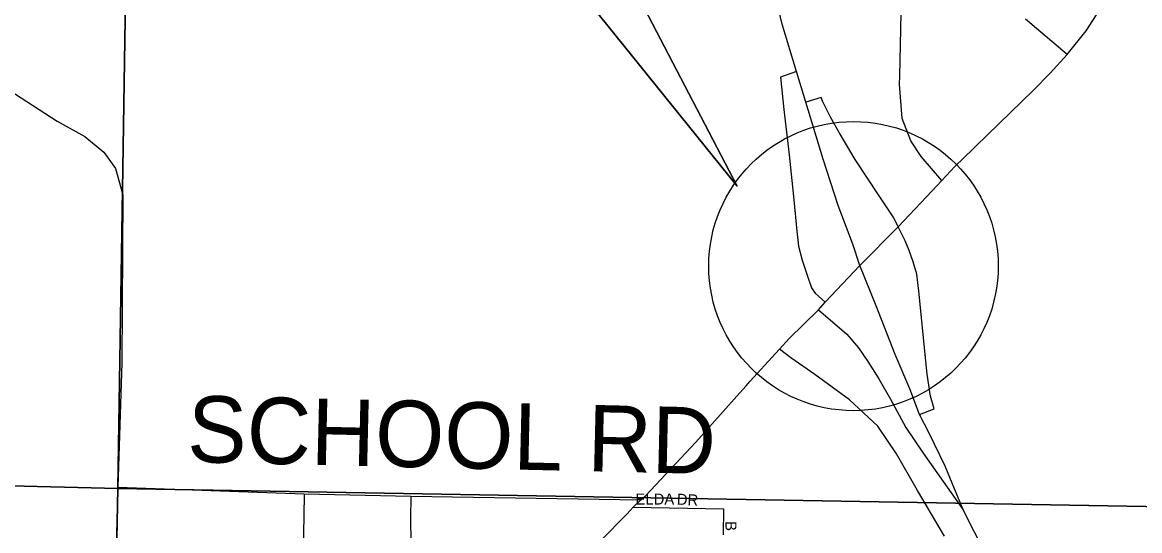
# Model space of a CAD drawing. Extents: x 0 to 34, y -2.3 to 22.
# Drawn here: x 5.22 to 6.175, y 15.386 to 15.821 of the extents above; entities that cross this region are included whole.
import ezdxf

# ---------------------------------------------------------------- set-up
doc = ezdxf.new("R2010")
doc.units = 0
for name, color, linetype in [('GM_X_County_Road', 7, 'Continuous'), ('GM_X_County_Road_Text', 7, 'Continuous'), ('GM_X_Interchange_Ramps', 7, 'Continuous'), ('GM_X_Section', 7, 'Continuous'), ('GM_X_State_Route', 7, 'Continuous'), ('GM_X_Township_Road', 7, 'Continuous'), ('GM_X_Township_Subdivision', 7, 'Continuous'), ('GM_X_Township_Subdivision_Text', 7, 'Continuous'), ('GM_X_US_Route', 7, 'Continuous'), ('SH_Text', 7, 'Continuous')]:
    doc.layers.add(name, color=color, linetype=linetype)

msp = doc.modelspace()

# ---------------------------------------------------------------- linework, layer by layer
at = {"layer": 'GM_X_County_Road'}
for p, q in [((5.13388, 15.8111), (5.24961, 15.73664)), ((5.24961, 15.73664), (5.27317, 15.72357)), ((5.27317, 15.72357), (5.28951, 15.71015)), ((5.28951, 15.71015), (5.29931, 15.69623)), ((5.29931, 15.69623), (5.30567, 15.67364)), ((5.30567, 15.67364), (5.30481, 15.52995)), ((5.30481, 15.52995), (5.30141, 15.42345)), ((5.30141, 15.42345), (5.29588, 15.22751)), ((5.30141, 15.42345), (5.46049, 15.41784)), ((5.46049, 15.41784), (5.5518, 15.41586)), ((5.5518, 15.41586), (5.74844, 15.41261))]:
    msp.add_line(p, q, dxfattribs=at)
at = {"layer": 'GM_X_Interchange_Ramps'}
for p, q in [((5.88133, 15.77914), (5.86757, 15.77434)), ((5.86757, 15.77434), (5.8706, 15.74657)), ((5.90238, 15.75687), (5.88938, 15.75297)), ((5.90394, 15.75313), (5.90238, 15.75687)), ((5.8706, 15.74657), (5.87504, 15.70775)), ((5.91043, 15.73995), (5.90394, 15.75313)), ((5.91785, 15.72682), (5.91043, 15.73995)), ((5.93165, 15.70393), (5.91785, 15.72682)), ((5.87504, 15.70775), (5.87906, 15.66943)), ((5.95154, 15.67369), (5.93165, 15.70393)), ((5.96443, 15.6539), (5.95154, 15.67369)), ((5.87906, 15.66943), (5.88158, 15.64252)), ((5.96829, 15.6463), (5.96443, 15.6539)), ((5.88158, 15.64252), (5.88316, 15.62961)), ((5.971, 15.64065), (5.96829, 15.6463)), ((5.97425, 15.63415), (5.971, 15.64065)), ((5.97769, 15.62606), (5.97425, 15.63415)), ((5.88316, 15.62961), (5.88628, 15.61771)), ((5.9812, 15.61643), (5.97769, 15.62606)), ((5.88628, 15.61771), (5.89056, 15.6049)), ((5.98421, 15.60565), (5.9812, 15.61643)), ((5.89056, 15.6049), (5.89432, 15.59408)), ((5.98586, 15.59117), (5.98421, 15.60565)), ((5.89432, 15.59408), (5.89736, 15.58942)), ((5.89736, 15.58942), (5.90591, 15.58167)), ((5.98813, 15.56876), (5.98586, 15.59117)), ((5.99131, 15.53692), (5.98813, 15.56876)), ((5.99316, 15.52032), (5.99131, 15.53692)), ((5.99599, 15.50128), (5.99316, 15.52032)), ((5.99893, 15.49052), (5.99599, 15.50128)), ((5.98655, 15.48577), (5.99893, 15.49052))]:
    msp.add_line(p, q, dxfattribs=at)
at = {"layer": 'GM_X_Section'}
for p, q in [((5.31637, 16.38127), (5.30144, 15.42241)), ((5.30144, 15.42241), (5.31637, 16.38127)), ((5.30144, 15.42241), (4.29924, 15.44635)), ((4.29924, 15.44635), (5.30144, 15.42241)), ((5.30144, 15.42241), (5.2785, 14.42965)), ((5.2785, 14.42965), (5.30144, 15.42241)), ((6.48214, 15.40173), (5.30144, 15.42241)), ((5.30144, 15.42241), (6.48214, 15.40173))]:
    msp.add_line(p, q, dxfattribs=at)
at = {"layer": 'GM_X_State_Route'}
for p, q in [((6.12891, 15.81387), (6.14031, 15.83145)), ((6.11275, 15.79357), (6.12891, 15.81387)), ((6.09814, 15.77772), (6.11275, 15.79357)), ((6.08365, 15.7629), (6.09814, 15.77772)), ((6.06427, 15.74418), (6.08365, 15.7629)), ((6.03463, 15.7152), (6.06427, 15.74418)), ((6.01673, 15.69778), (6.03224, 15.71287)), ((6.03224, 15.71287), (6.03463, 15.7152)), ((6.00549, 15.68589), (6.01673, 15.69778)), ((5.99247, 15.67188), (6.00549, 15.68589)), ((5.96829, 15.6463), (5.99247, 15.67188)), ((5.9355, 15.61313), (5.96829, 15.6463)), ((5.90591, 15.58167), (5.9355, 15.61313)), ((5.87504, 15.5507), (5.90021, 15.57511)), ((5.90021, 15.57511), (5.90591, 15.58167)), ((5.90021, 15.57511), (5.92452, 15.55438)), ((5.86678, 15.54156), (5.87504, 15.5507)), ((5.92452, 15.55438), (5.93439, 15.54274)), ((5.8415, 15.51395), (5.86678, 15.54156)), ((5.93439, 15.54274), (5.94233, 15.53093)), ((5.94233, 15.53093), (5.95185, 15.51612)), ((5.83035, 15.50129), (5.83829, 15.51031)), ((5.83829, 15.51031), (5.8415, 15.51395)), ((5.95185, 15.51612), (5.96172, 15.49885)), ((5.79523, 15.46204), (5.83035, 15.50129)), ((5.96172, 15.49885), (5.97494, 15.47452)), ((5.97494, 15.47452), (5.98975, 15.45266)), ((5.75237, 15.41616), (5.79523, 15.46204)), ((5.98975, 15.45266), (6.02395, 15.40418)), ((5.74193, 15.40635), (5.74844, 15.41261)), ((5.74844, 15.41261), (5.75237, 15.41616)), ((5.73658, 15.40087), (5.74193, 15.40635)), ((5.71385, 15.37762), (5.73658, 15.40087))]:
    msp.add_line(p, q, dxfattribs=at)
at = {"layer": 'GM_X_Township_Road'}
for p, q in [((5.9696, 15.77502), (5.97529, 16.04569)), ((5.96945, 15.76815), (5.9696, 15.77502)), ((5.97159, 15.73877), (5.96945, 15.76815)), ((5.97917, 15.71973), (5.97159, 15.73877)), ((5.98799, 15.70651), (5.97917, 15.71973)), ((6.00549, 15.68589), (5.98799, 15.70651)), ((5.87641, 15.53424), (5.86678, 15.54156)), ((5.89696, 15.52), (5.87641, 15.53424)), ((5.92665, 15.49839), (5.89696, 15.52)), ((5.95103, 15.47579), (5.92665, 15.49839)), ((5.96676, 15.45197), (5.95103, 15.47579)), ((5.98471, 15.42061), (5.96676, 15.45197)), ((6.00775, 15.38173), (5.98471, 15.42061))]:
    msp.add_line(p, q, dxfattribs=at)
at = {"layer": 'GM_X_Township_Subdivision'}
for p, q in [((6.11275, 15.79357), (6.07714, 15.82396)), ((5.46049, 15.41784), (5.46023, 15.39876)), ((5.5518, 15.41586), (5.55139, 15.39654)), ((5.74193, 15.40635), (5.81899, 15.40504)), ((5.81899, 15.40504), (5.81861, 15.38275)), ((5.46023, 15.39876), (5.45984, 15.37059)), ((5.55139, 15.39654), (5.55136, 15.39515)), ((5.55136, 15.39515), (5.55165, 15.37807))]:
    msp.add_line(p, q, dxfattribs=at)
at = {"layer": 'GM_X_US_Route'}
for p, q in [((5.86917, 15.81951), (5.86176, 15.85054)), ((5.88133, 15.77914), (5.86917, 15.81951)), ((5.88938, 15.75297), (5.88133, 15.77914)), ((5.90407, 15.70404), (5.88938, 15.75297)), ((5.91712, 15.66438), (5.90407, 15.70404)), ((5.92946, 15.63141), (5.91712, 15.66438)), ((5.9355, 15.61313), (5.92946, 15.63141)), ((5.94938, 15.5787), (5.9355, 15.61313)), ((5.96577, 15.5371), (5.94938, 15.5787)), ((5.97811, 15.50766), (5.96577, 15.5371)), ((5.98655, 15.48577), (5.97811, 15.50766)), ((5.99469, 15.46976), (5.98655, 15.48577)), ((6.00844, 15.44155), (5.99469, 15.46976)), ((6.02395, 15.40418), (6.00844, 15.44155)), ((6.04299, 15.36645), (6.02395, 15.40418))]:
    msp.add_line(p, q, dxfattribs=at)
at = {"layer": 'SH_Text'}
for points in [[(5.02099, 16.68544), (5.83077, 15.68102), (5.02099, 17.23424)], [(5.02099, 16.68544), (5.02099, 17.23424), (5.83077, 15.68102)]]:
    msp.add_lwpolyline(points, close=True, dxfattribs=at)
msp.add_circle((5.93008, 15.61268), 0.12368, dxfattribs=at)

# ---------------------------------------------------------------- texts
at = {"layer": 'GM_X_County_Road_Text'}
msp.add_text('SCHOOL RD', height=0.056818, rotation=358.67224, dxfattribs=at).set_placement((5.36029, 15.44516))
at = {"layer": 'GM_X_Township_Subdivision_Text'}
for s, rotation, p in [('ELDA', 0.00001, (5.7438, 15.40867)), ('DR', 356.98314, (5.77889, 15.40867)), ('B', 270.17606, (5.82059, 15.3945))]:
    msp.add_text(s, height=0.00947, rotation=rotation, dxfattribs=at).set_placement(p)

doc.saveas('drawing.dxf')
